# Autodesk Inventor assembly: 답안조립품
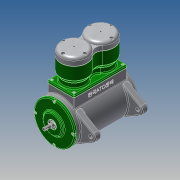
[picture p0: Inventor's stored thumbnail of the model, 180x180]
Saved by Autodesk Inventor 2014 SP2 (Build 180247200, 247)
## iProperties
Created: 2019-08
Part Number: 답안조립품
Document SubType Name: Assembly
Designer: kb542-10
Mass: 7633.06 g
Surface Area: 5241.59 cm^2
Volume: 2149.87 cm^3
Density: 3.55048 g/cm^3
Author: kb542-10
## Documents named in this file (18)
- C:\Users\kb542-10\Desktop\390804V1048\답안조립품.iam
- C:\Users\kb542-10\Desktop\390804V1048\본체.ipt
- C:\Users\kb542-10\Desktop\390804V1048\앞커버.ipt
- C:\Users\kb542-10\Desktop\390804V1048\크랭크축.ipt
- C:\Users\kb542-10\Desktop\390804V1048\베어링 12 x 28 x 8.ipt
- C:\Users\kb542-10\Desktop\390804V1048\오일 실 12 25 7.ipt
- C:\Users\kb542-10\Desktop\390804V1048\실린더 개스킷.ipt
- C:\Users\kb542-10\Desktop\390804V1048\실린더.ipt
- C:\Users\kb542-10\Desktop\390804V1048\피스톤.ipt
- C:\Users\kb542-10\Desktop\390804V1048\피스톤핀.ipt
- C:\Users\kb542-10\Desktop\390804V1048\커넥팅로드.ipt
- C:\Users\kb542-10\Desktop\390804V1048\커넥팅로드 엔드.ipt
- C:\Users\kb542-10\Desktop\390804V1048\육각 머리 볼트 M4 x 16.ipt
- C:\Users\kb542-10\Desktop\390804V1048\너트 M4.ipt
- C:\Users\kb542-10\Desktop\390804V1048\실린더헤드 개스킷.ipt
- C:\Users\kb542-10\Desktop\390804V1048\실린더헤드.ipt
- C:\Users\kb542-10\Desktop\390804V1048\볼트 M4 x 8.ipt
- C:\Users\kb542-10\Desktop\390804V1048\볼트 M5 x 20.ipt
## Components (4 placed, 2 different names)
1. 피스톤:1
2. 피스톤:2
3. 피스톤핀:1
4. 피스톤핀:2
